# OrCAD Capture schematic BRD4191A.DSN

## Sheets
1 06: Antenna Array: size A3; title: BG22 Dual Polarized Antenna Array Radio Board; rev: A03; company: Silicon Labs; note: BRD4191A; note: TAB; note: JSH
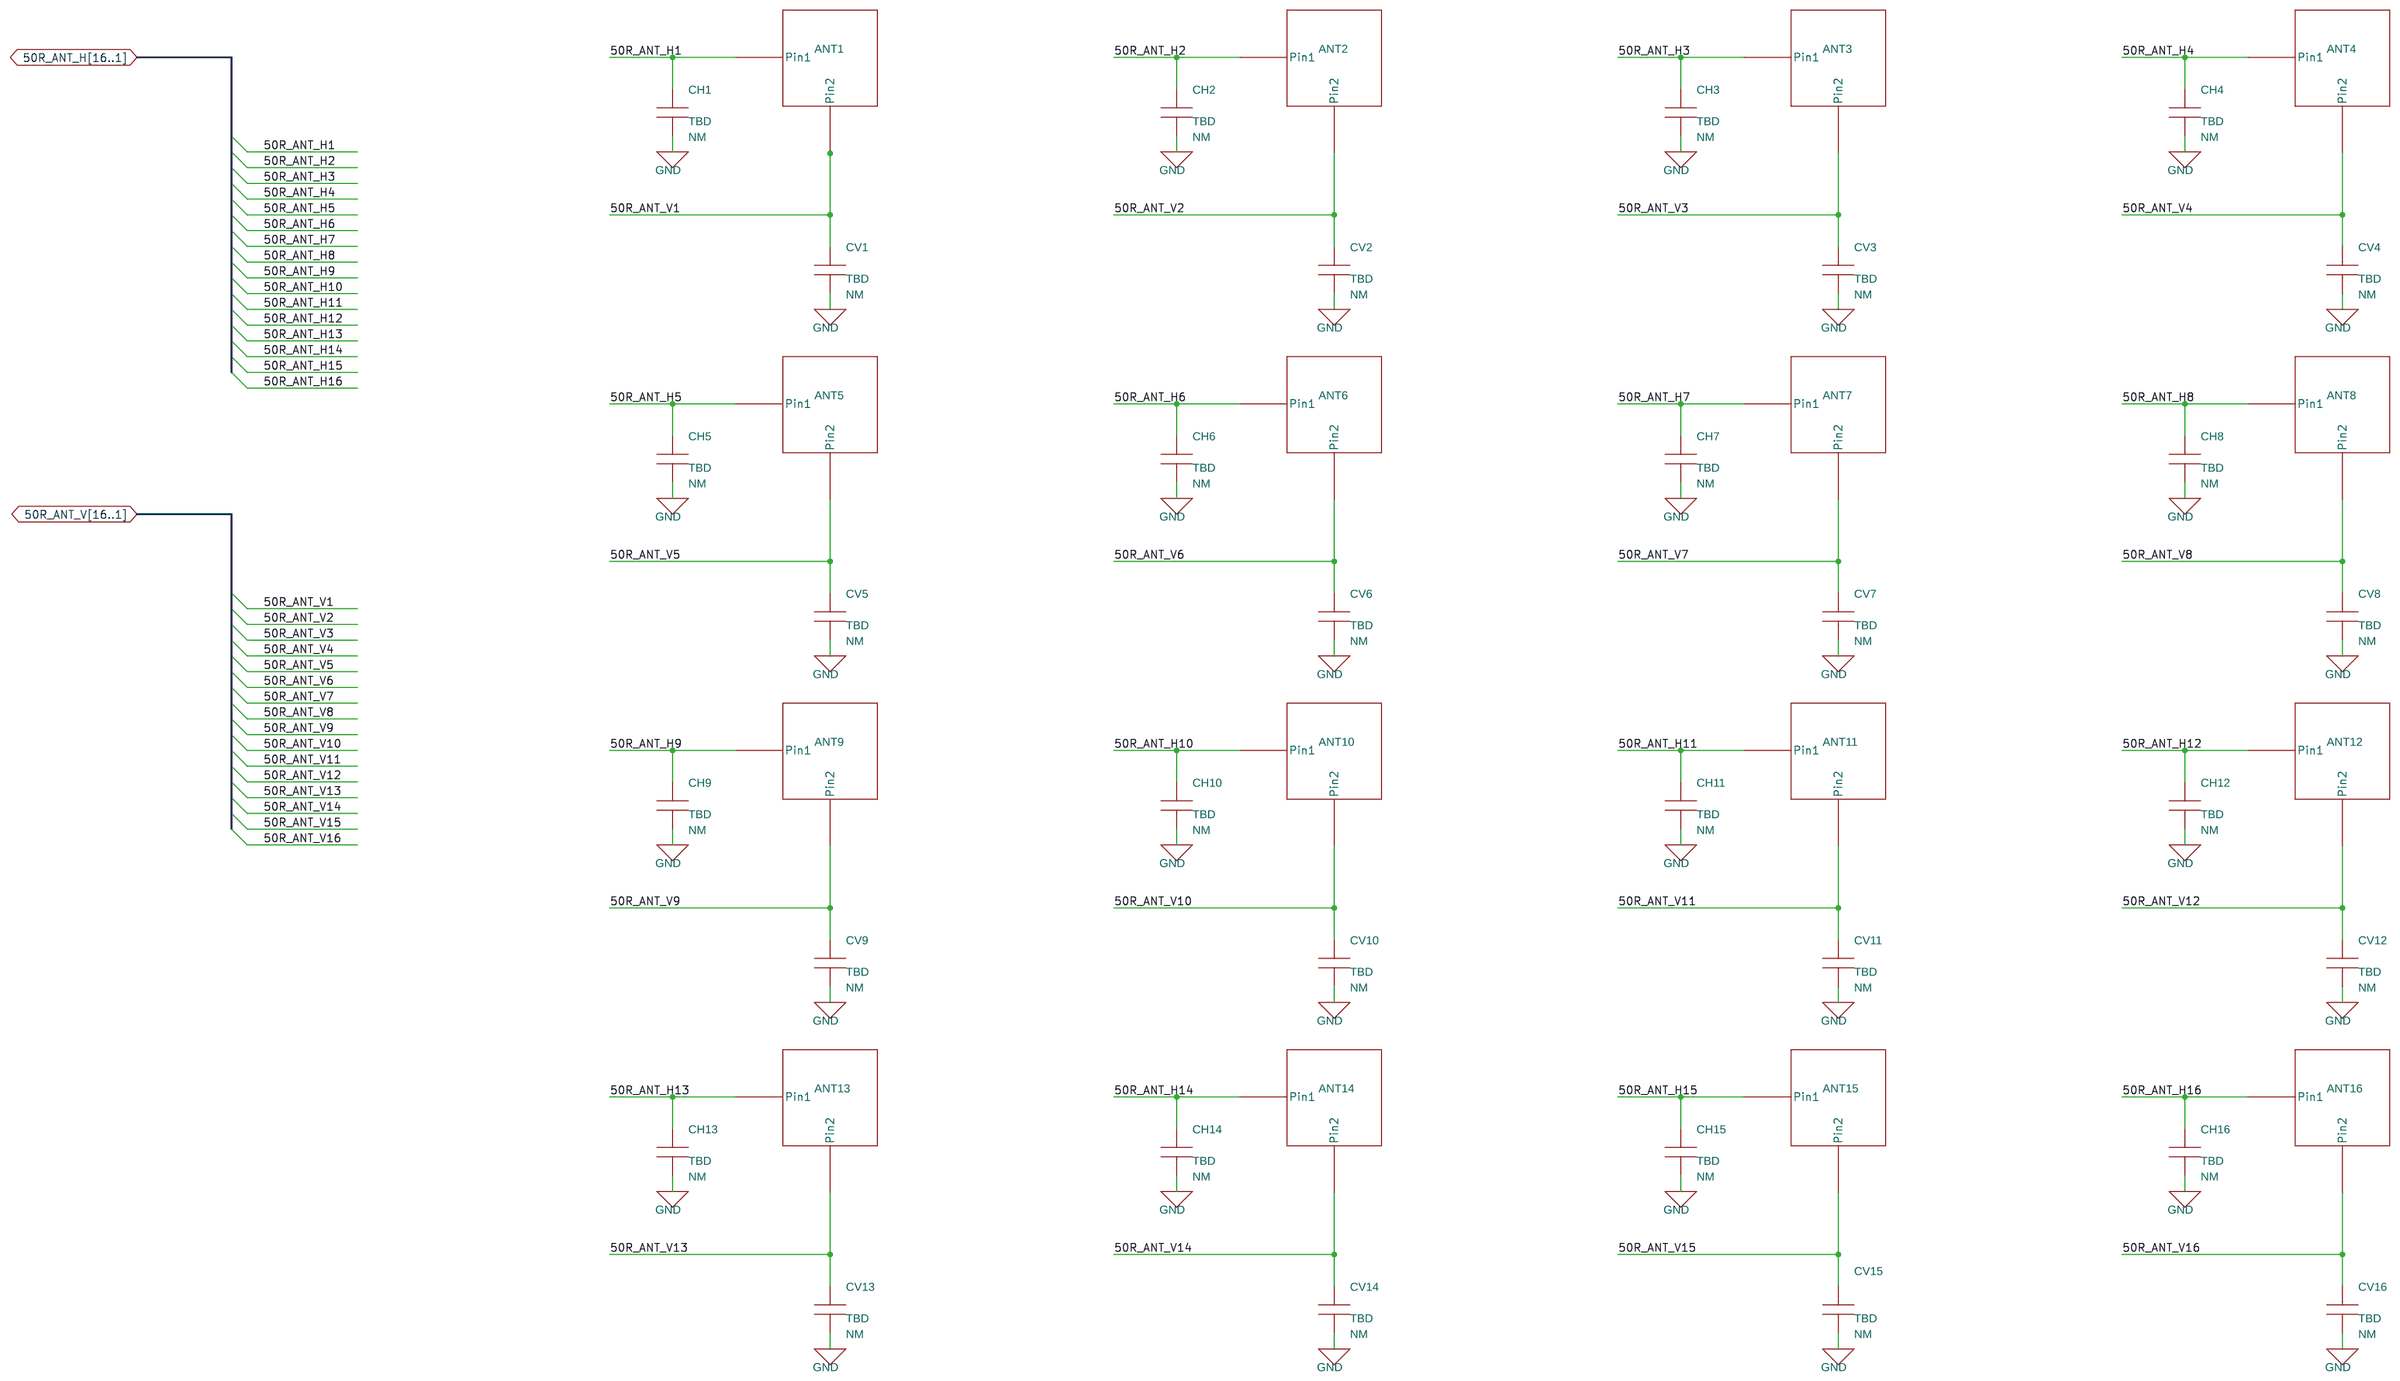
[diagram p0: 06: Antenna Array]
2 01: Title Page
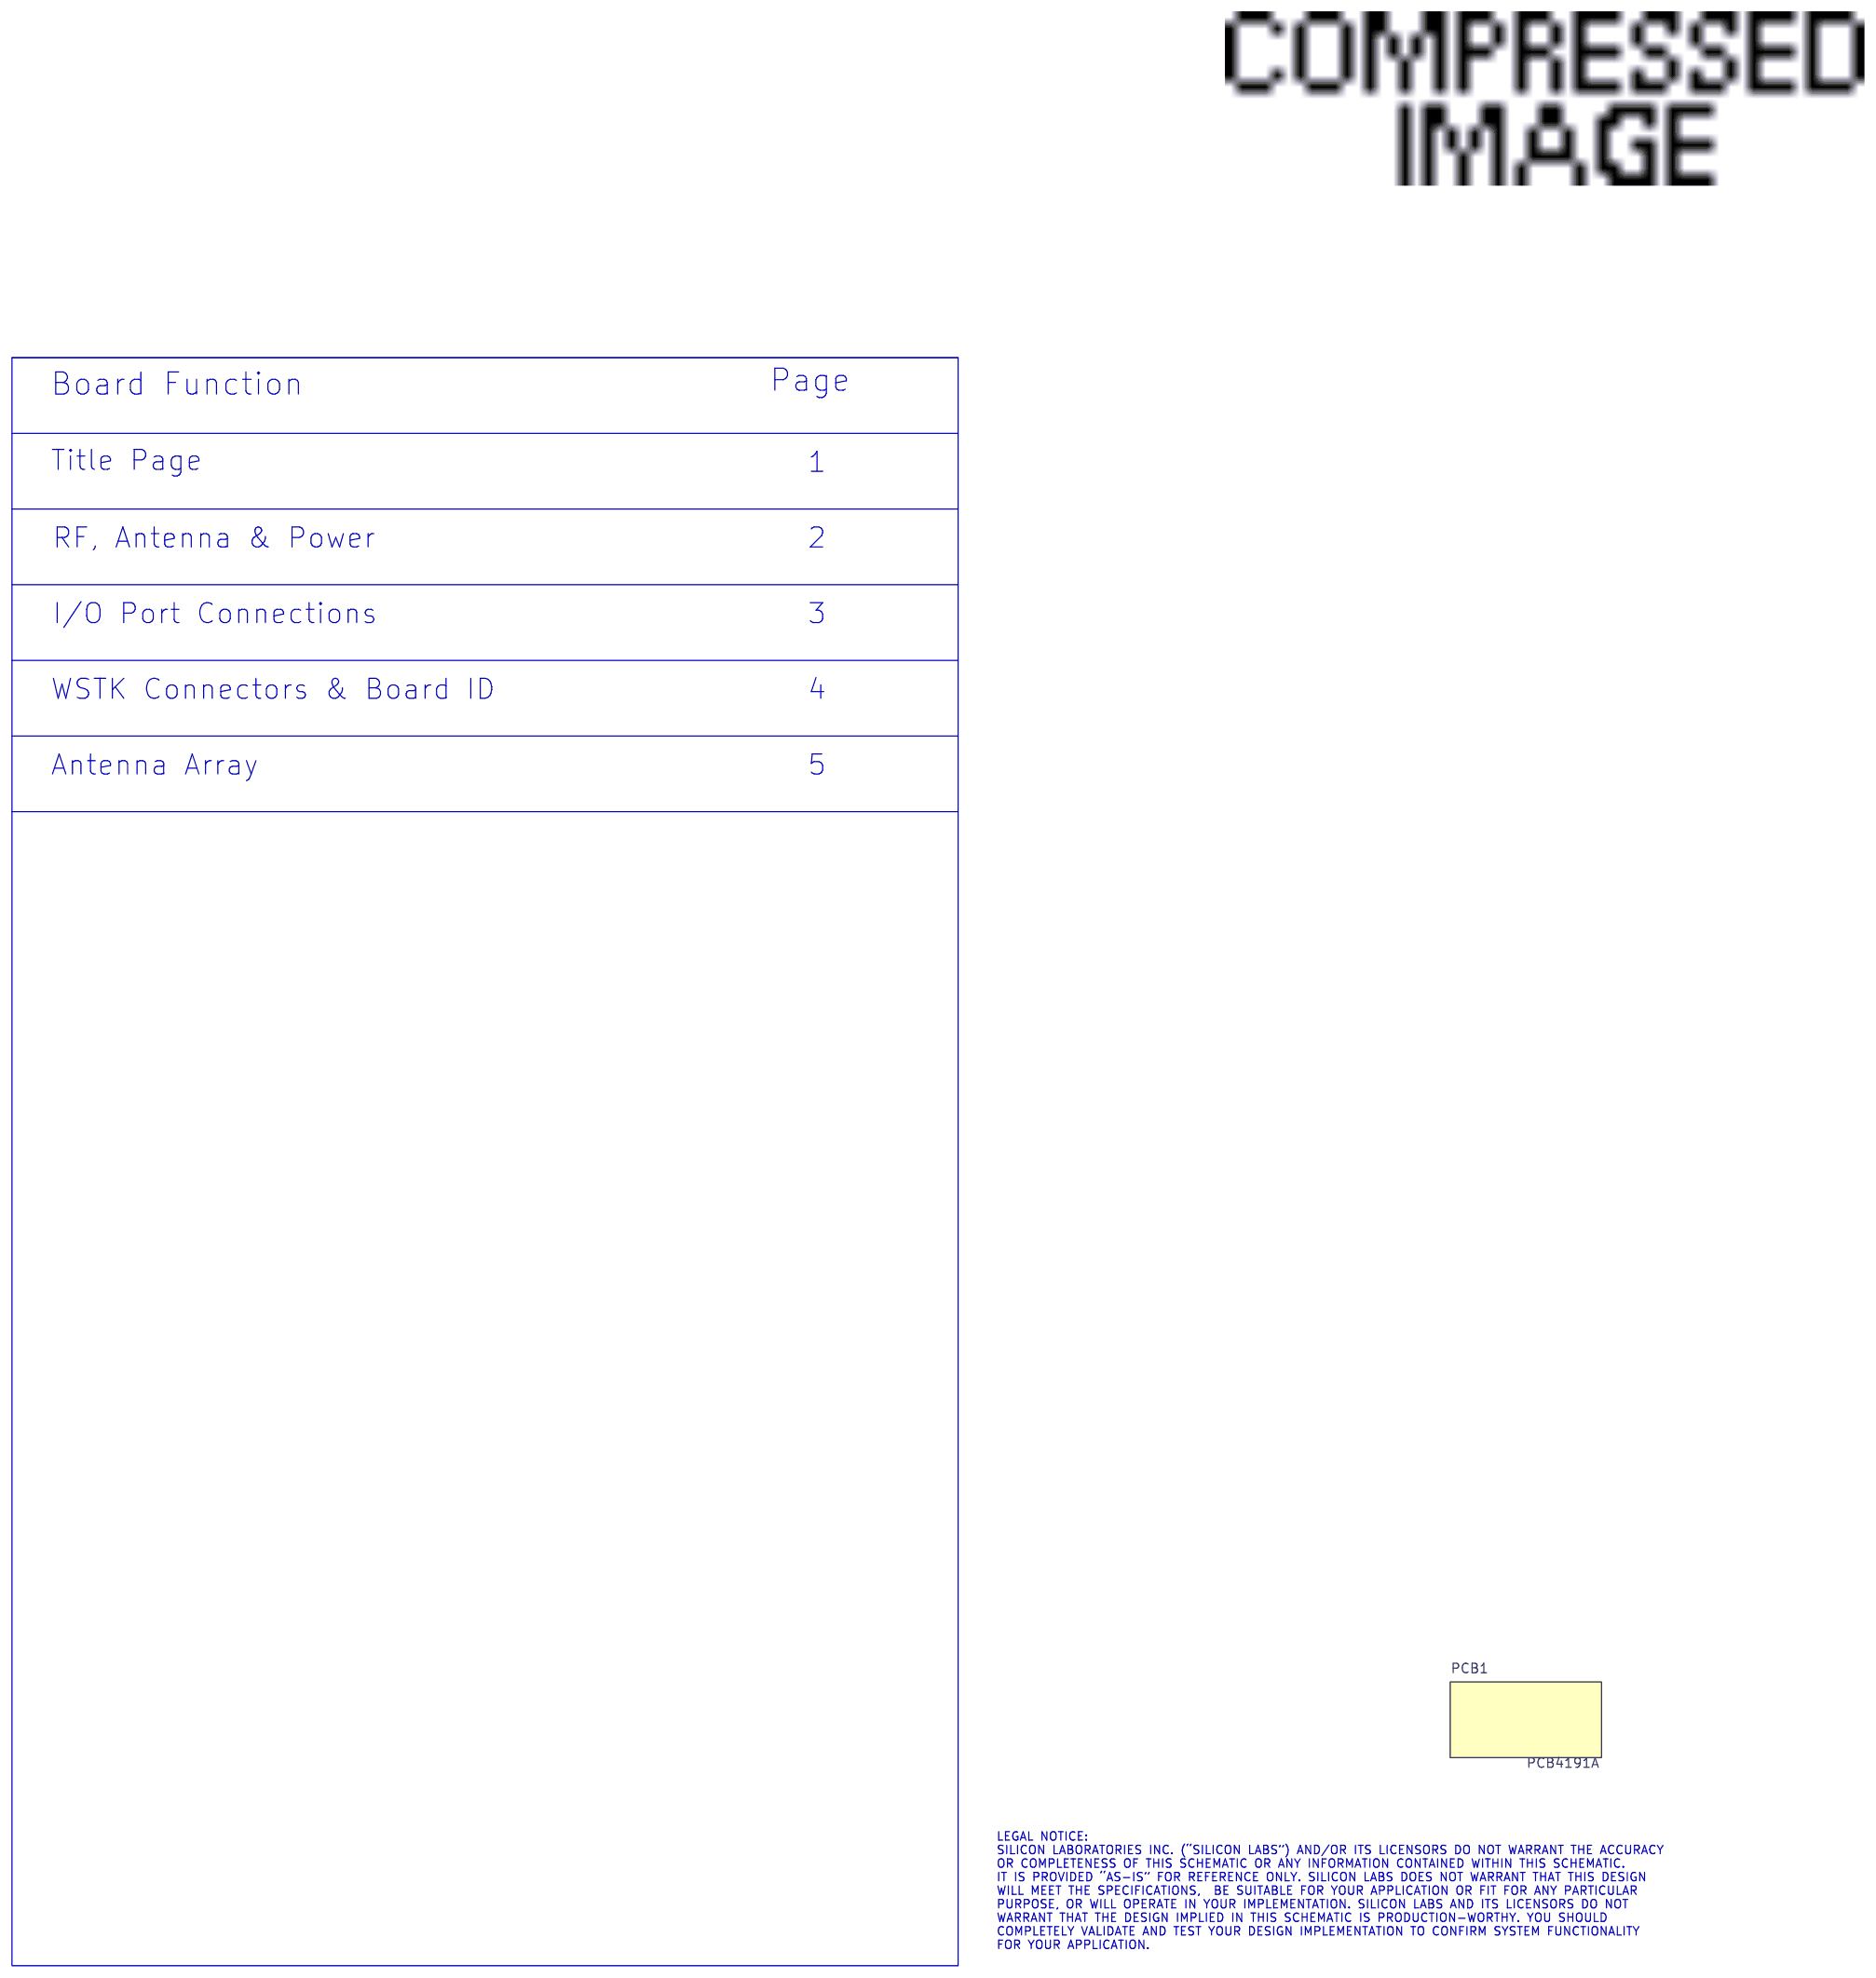
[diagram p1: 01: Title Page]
3 03: I/O Port Connections: size A3
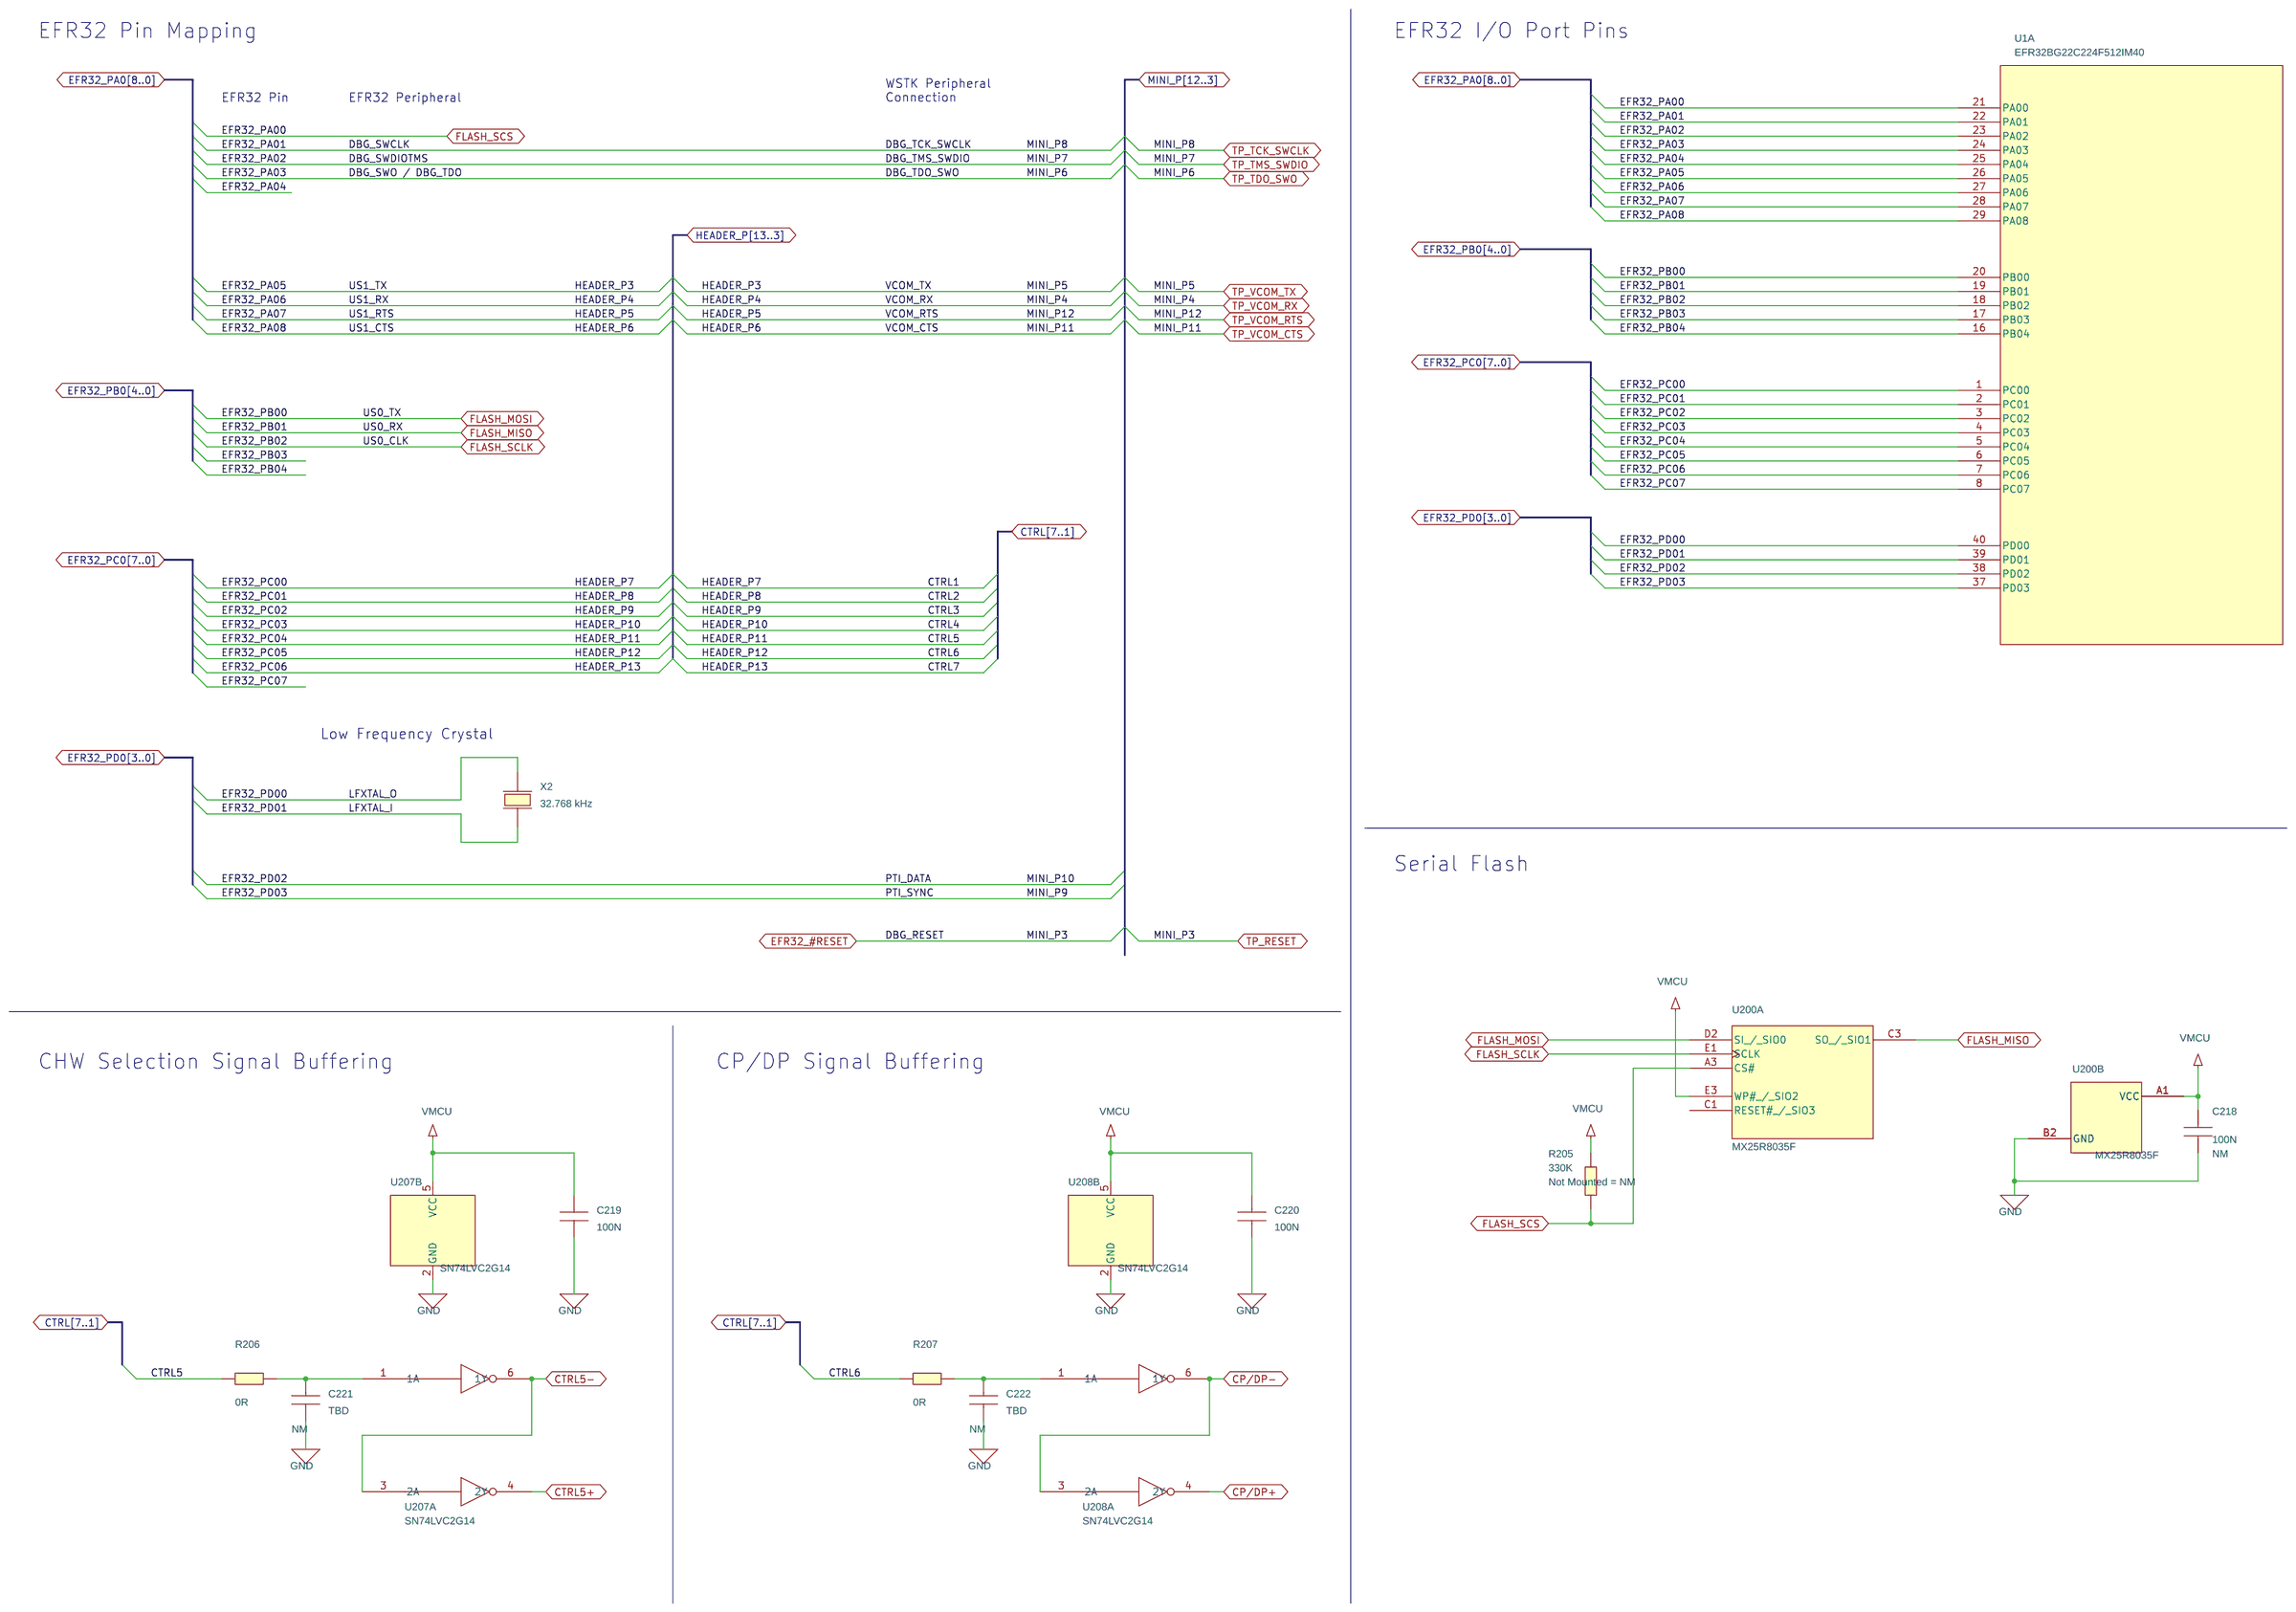
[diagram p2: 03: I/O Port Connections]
4 05: RF Feedline Network: size A3
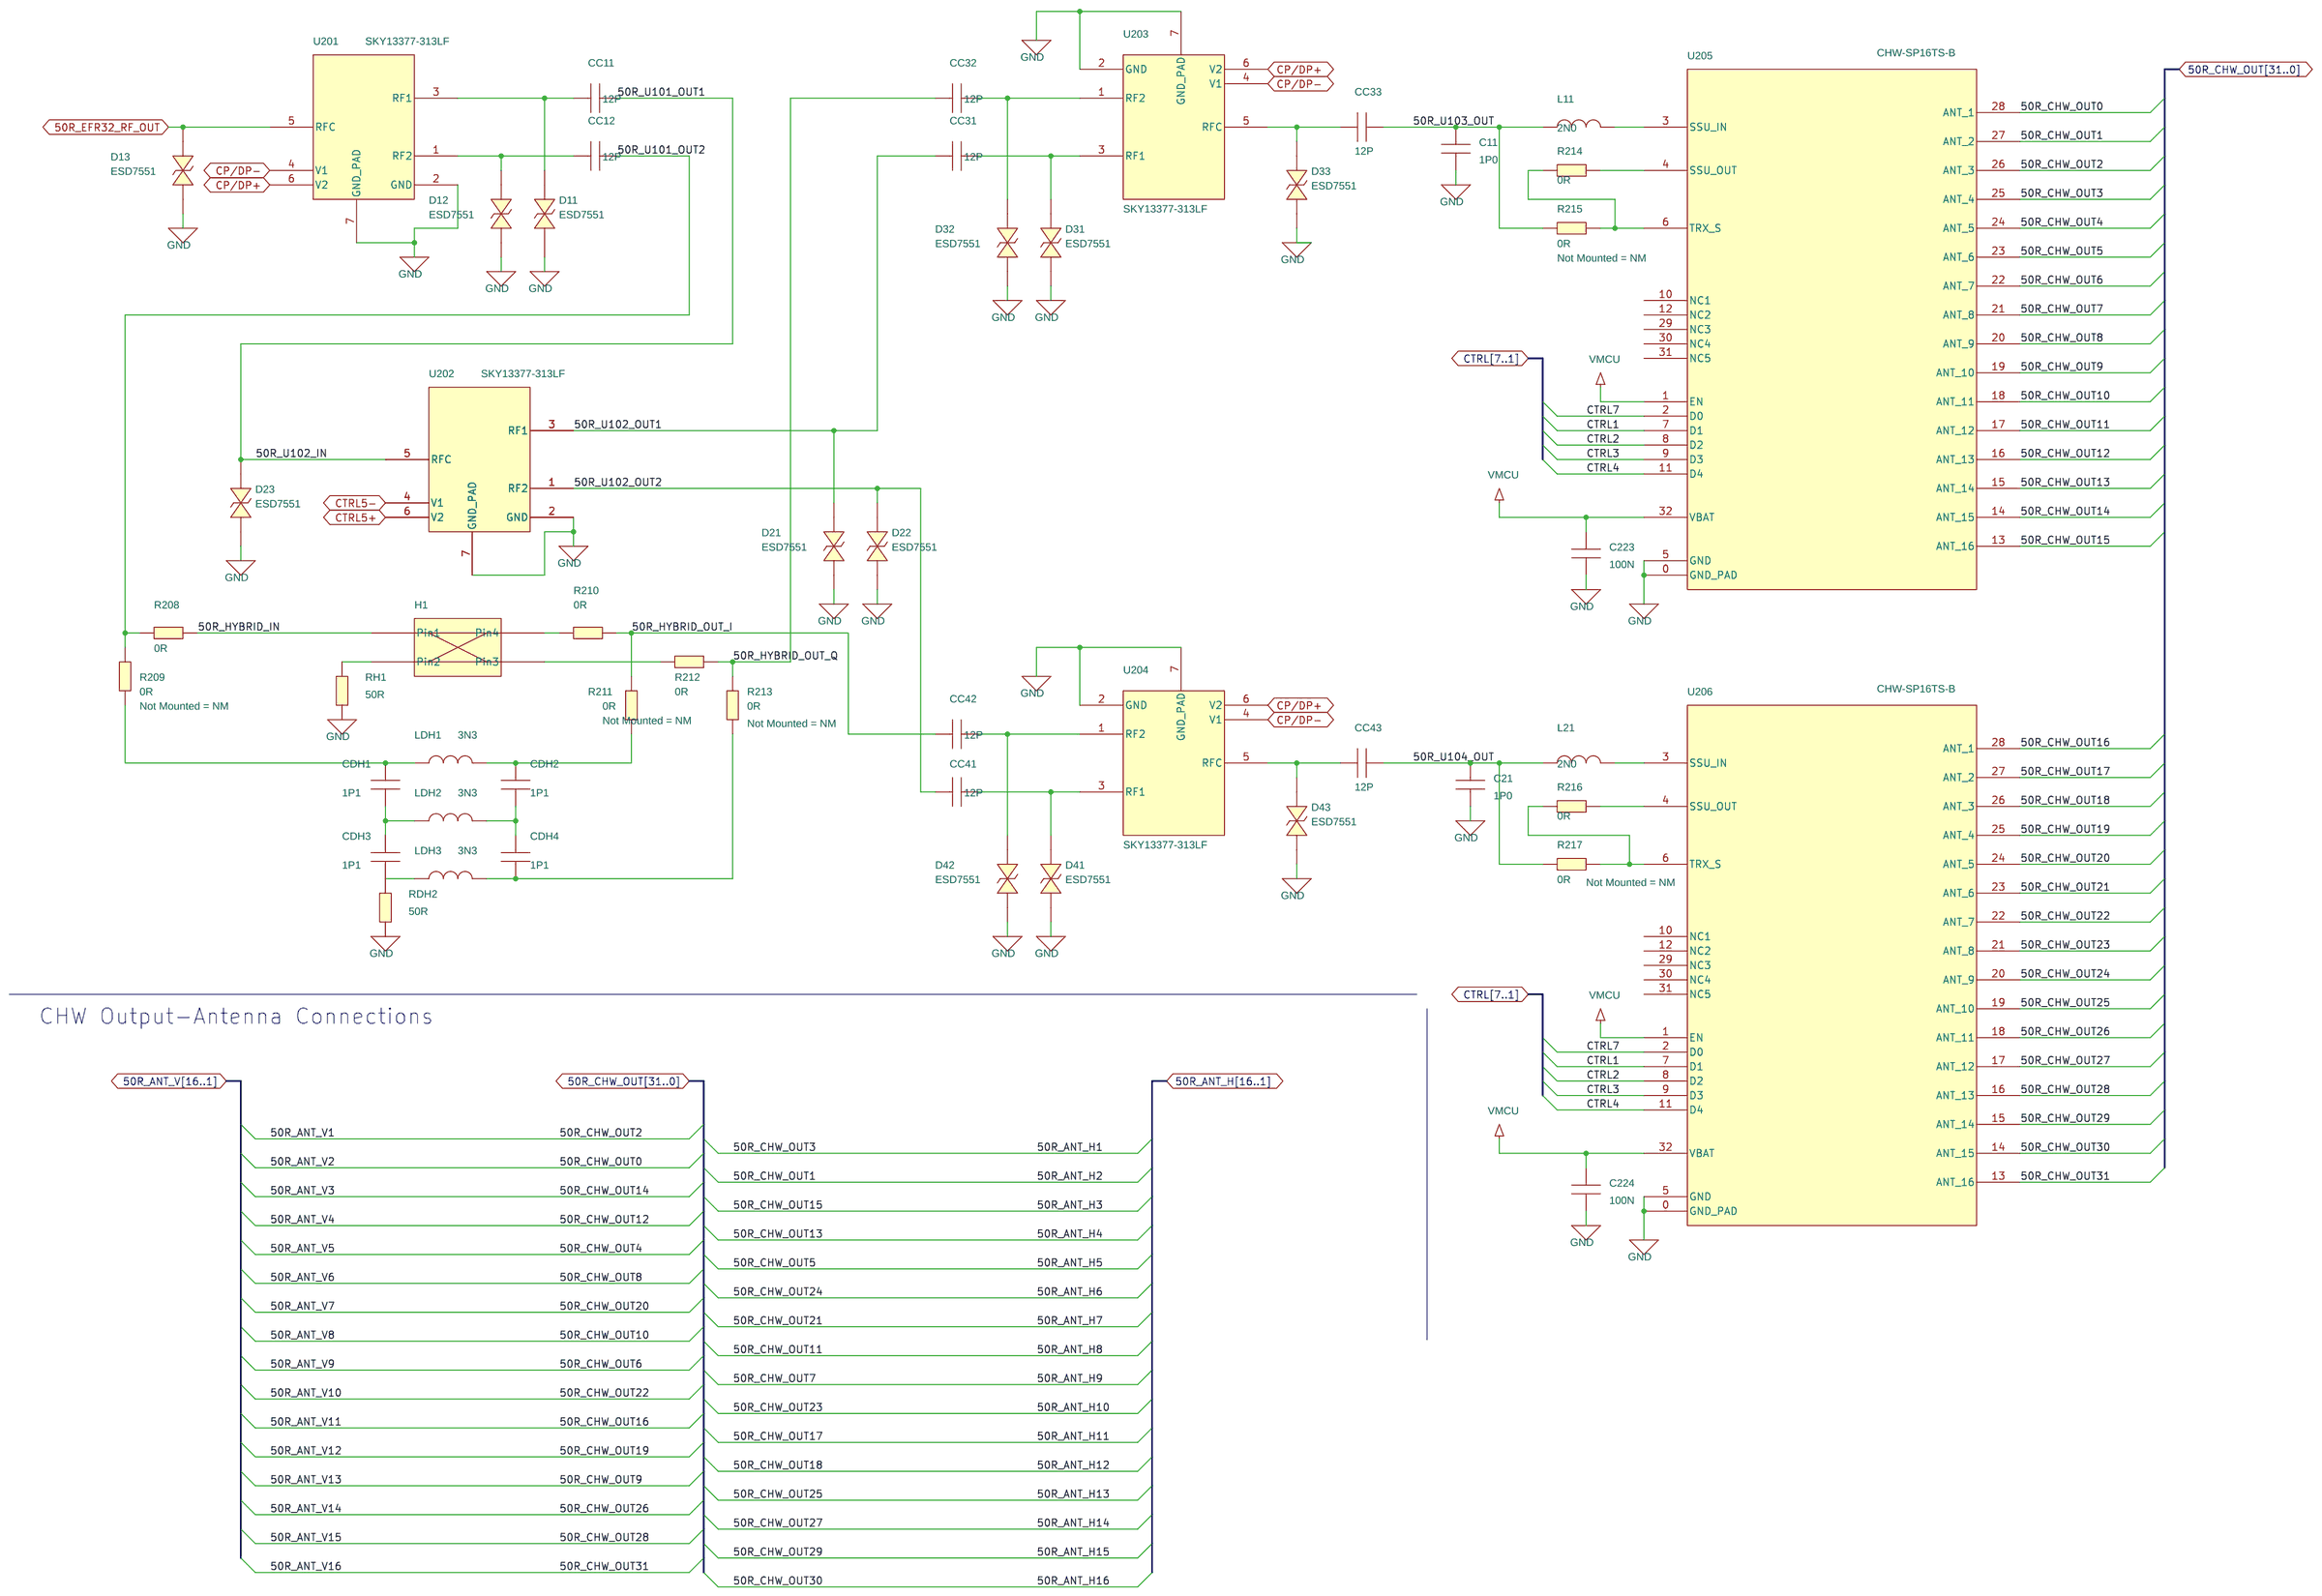
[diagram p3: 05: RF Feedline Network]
5 02: RF, Antenna and Power: size A3
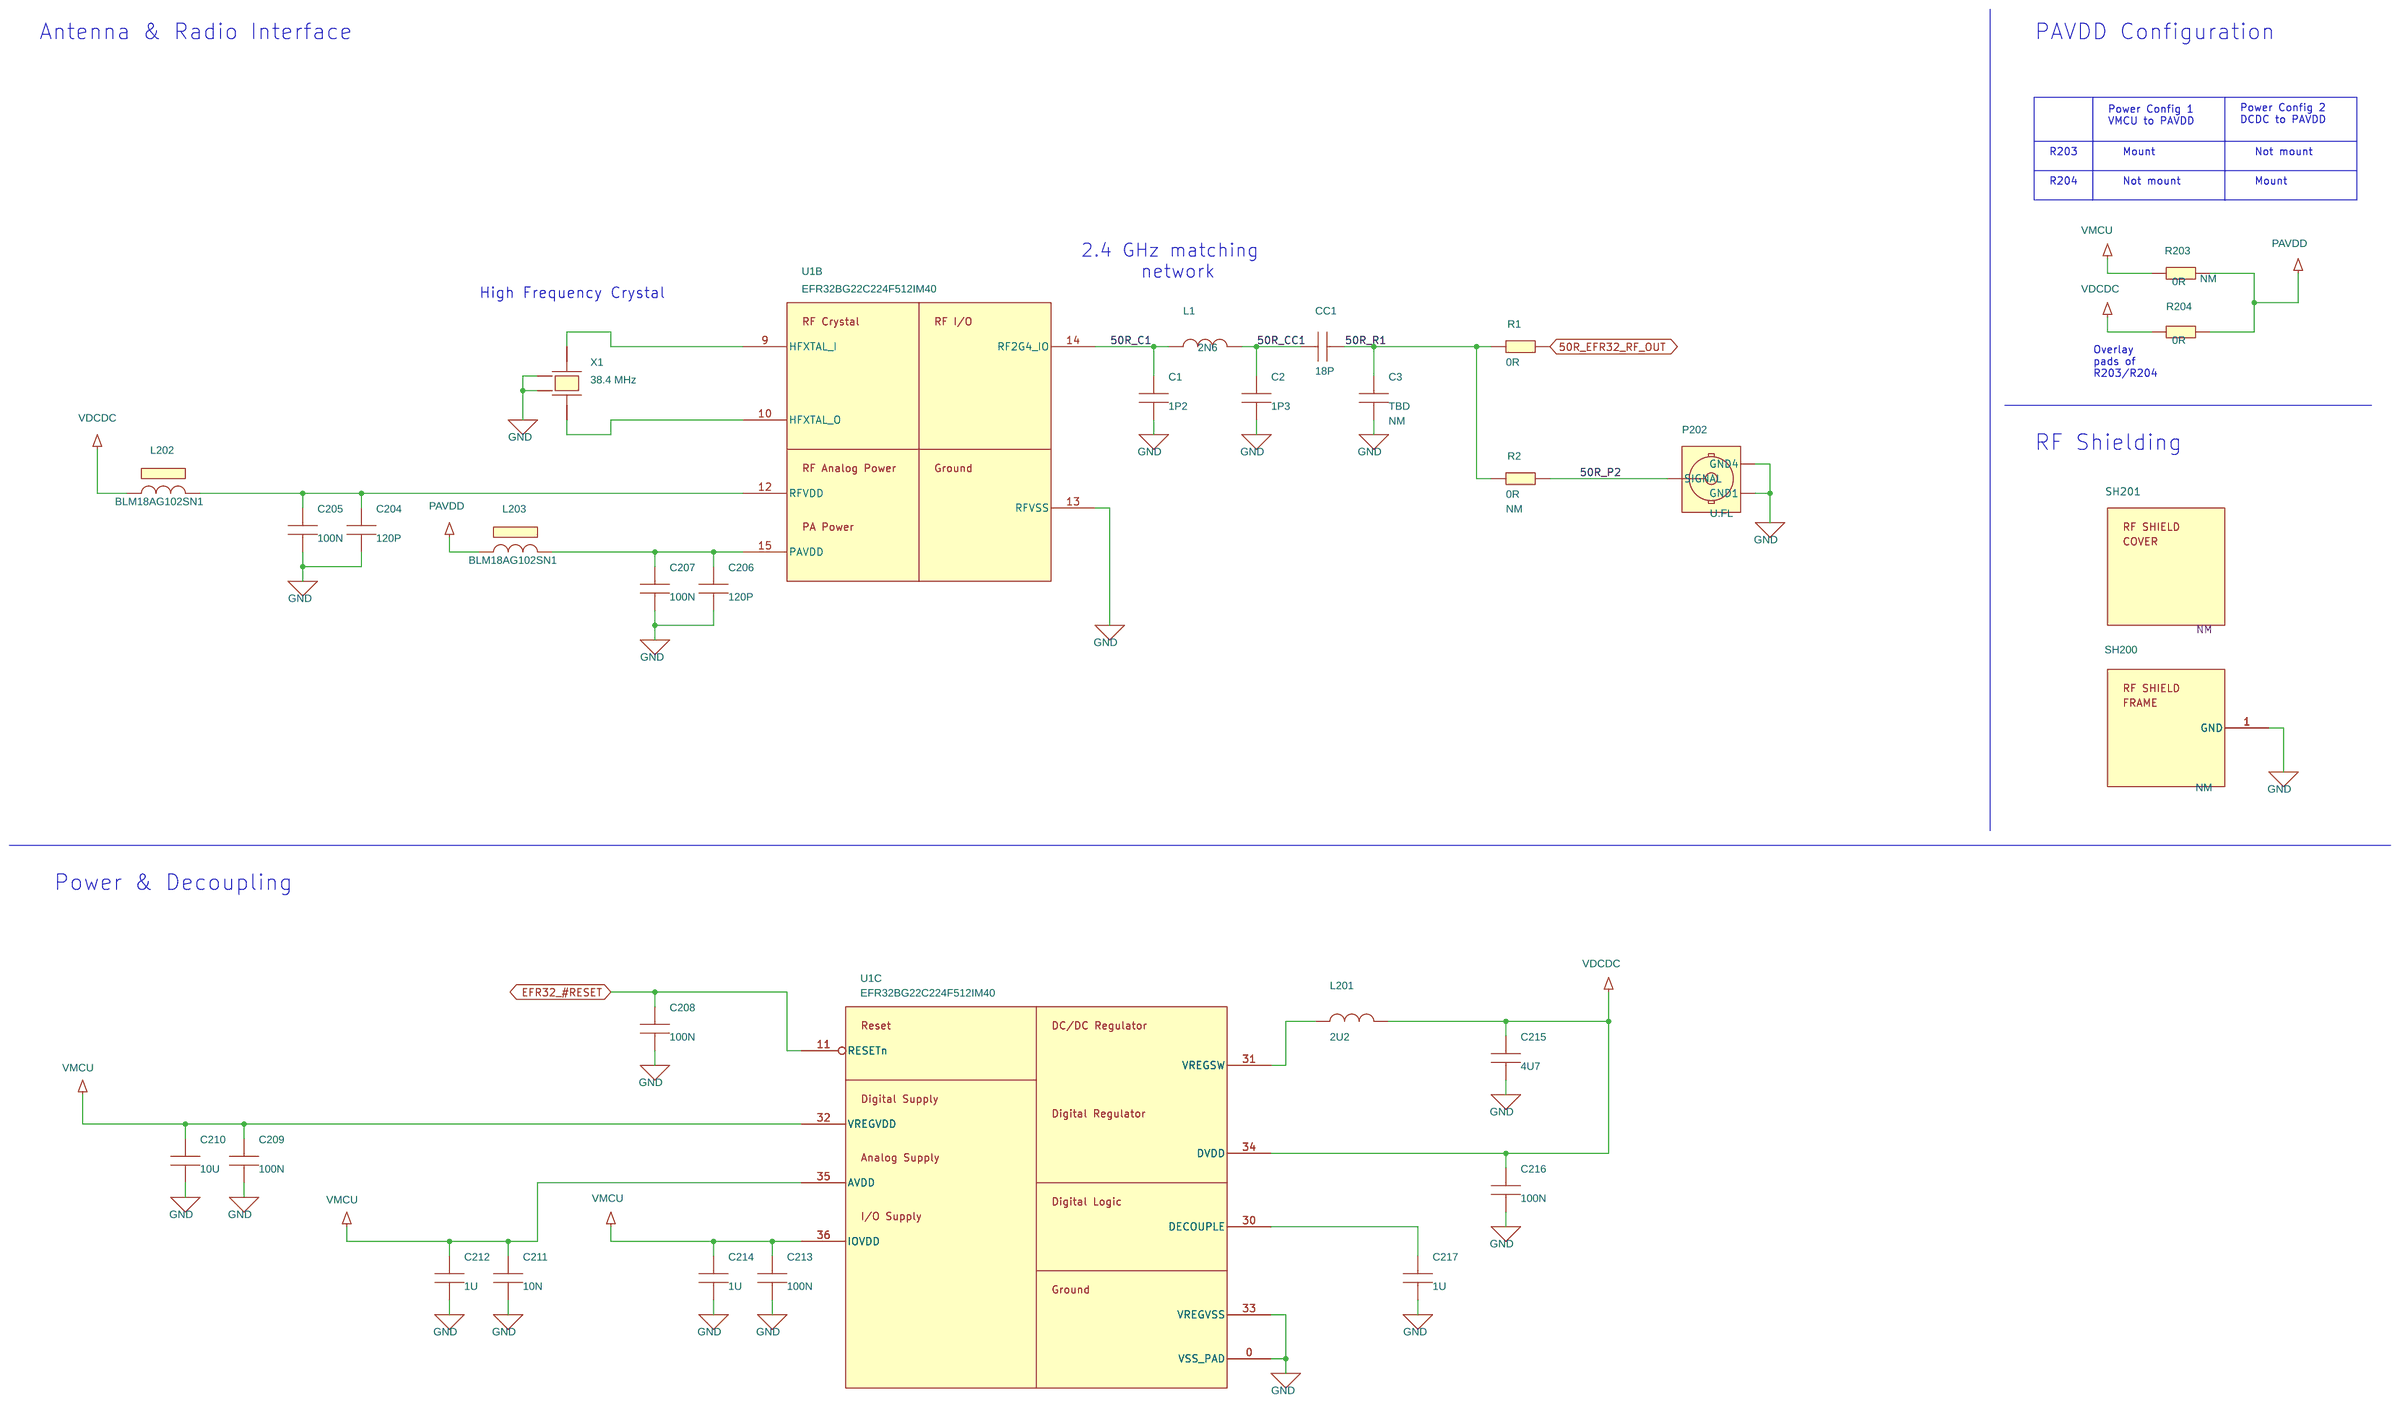
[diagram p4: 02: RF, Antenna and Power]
6 04: Board connection & TP: size A3
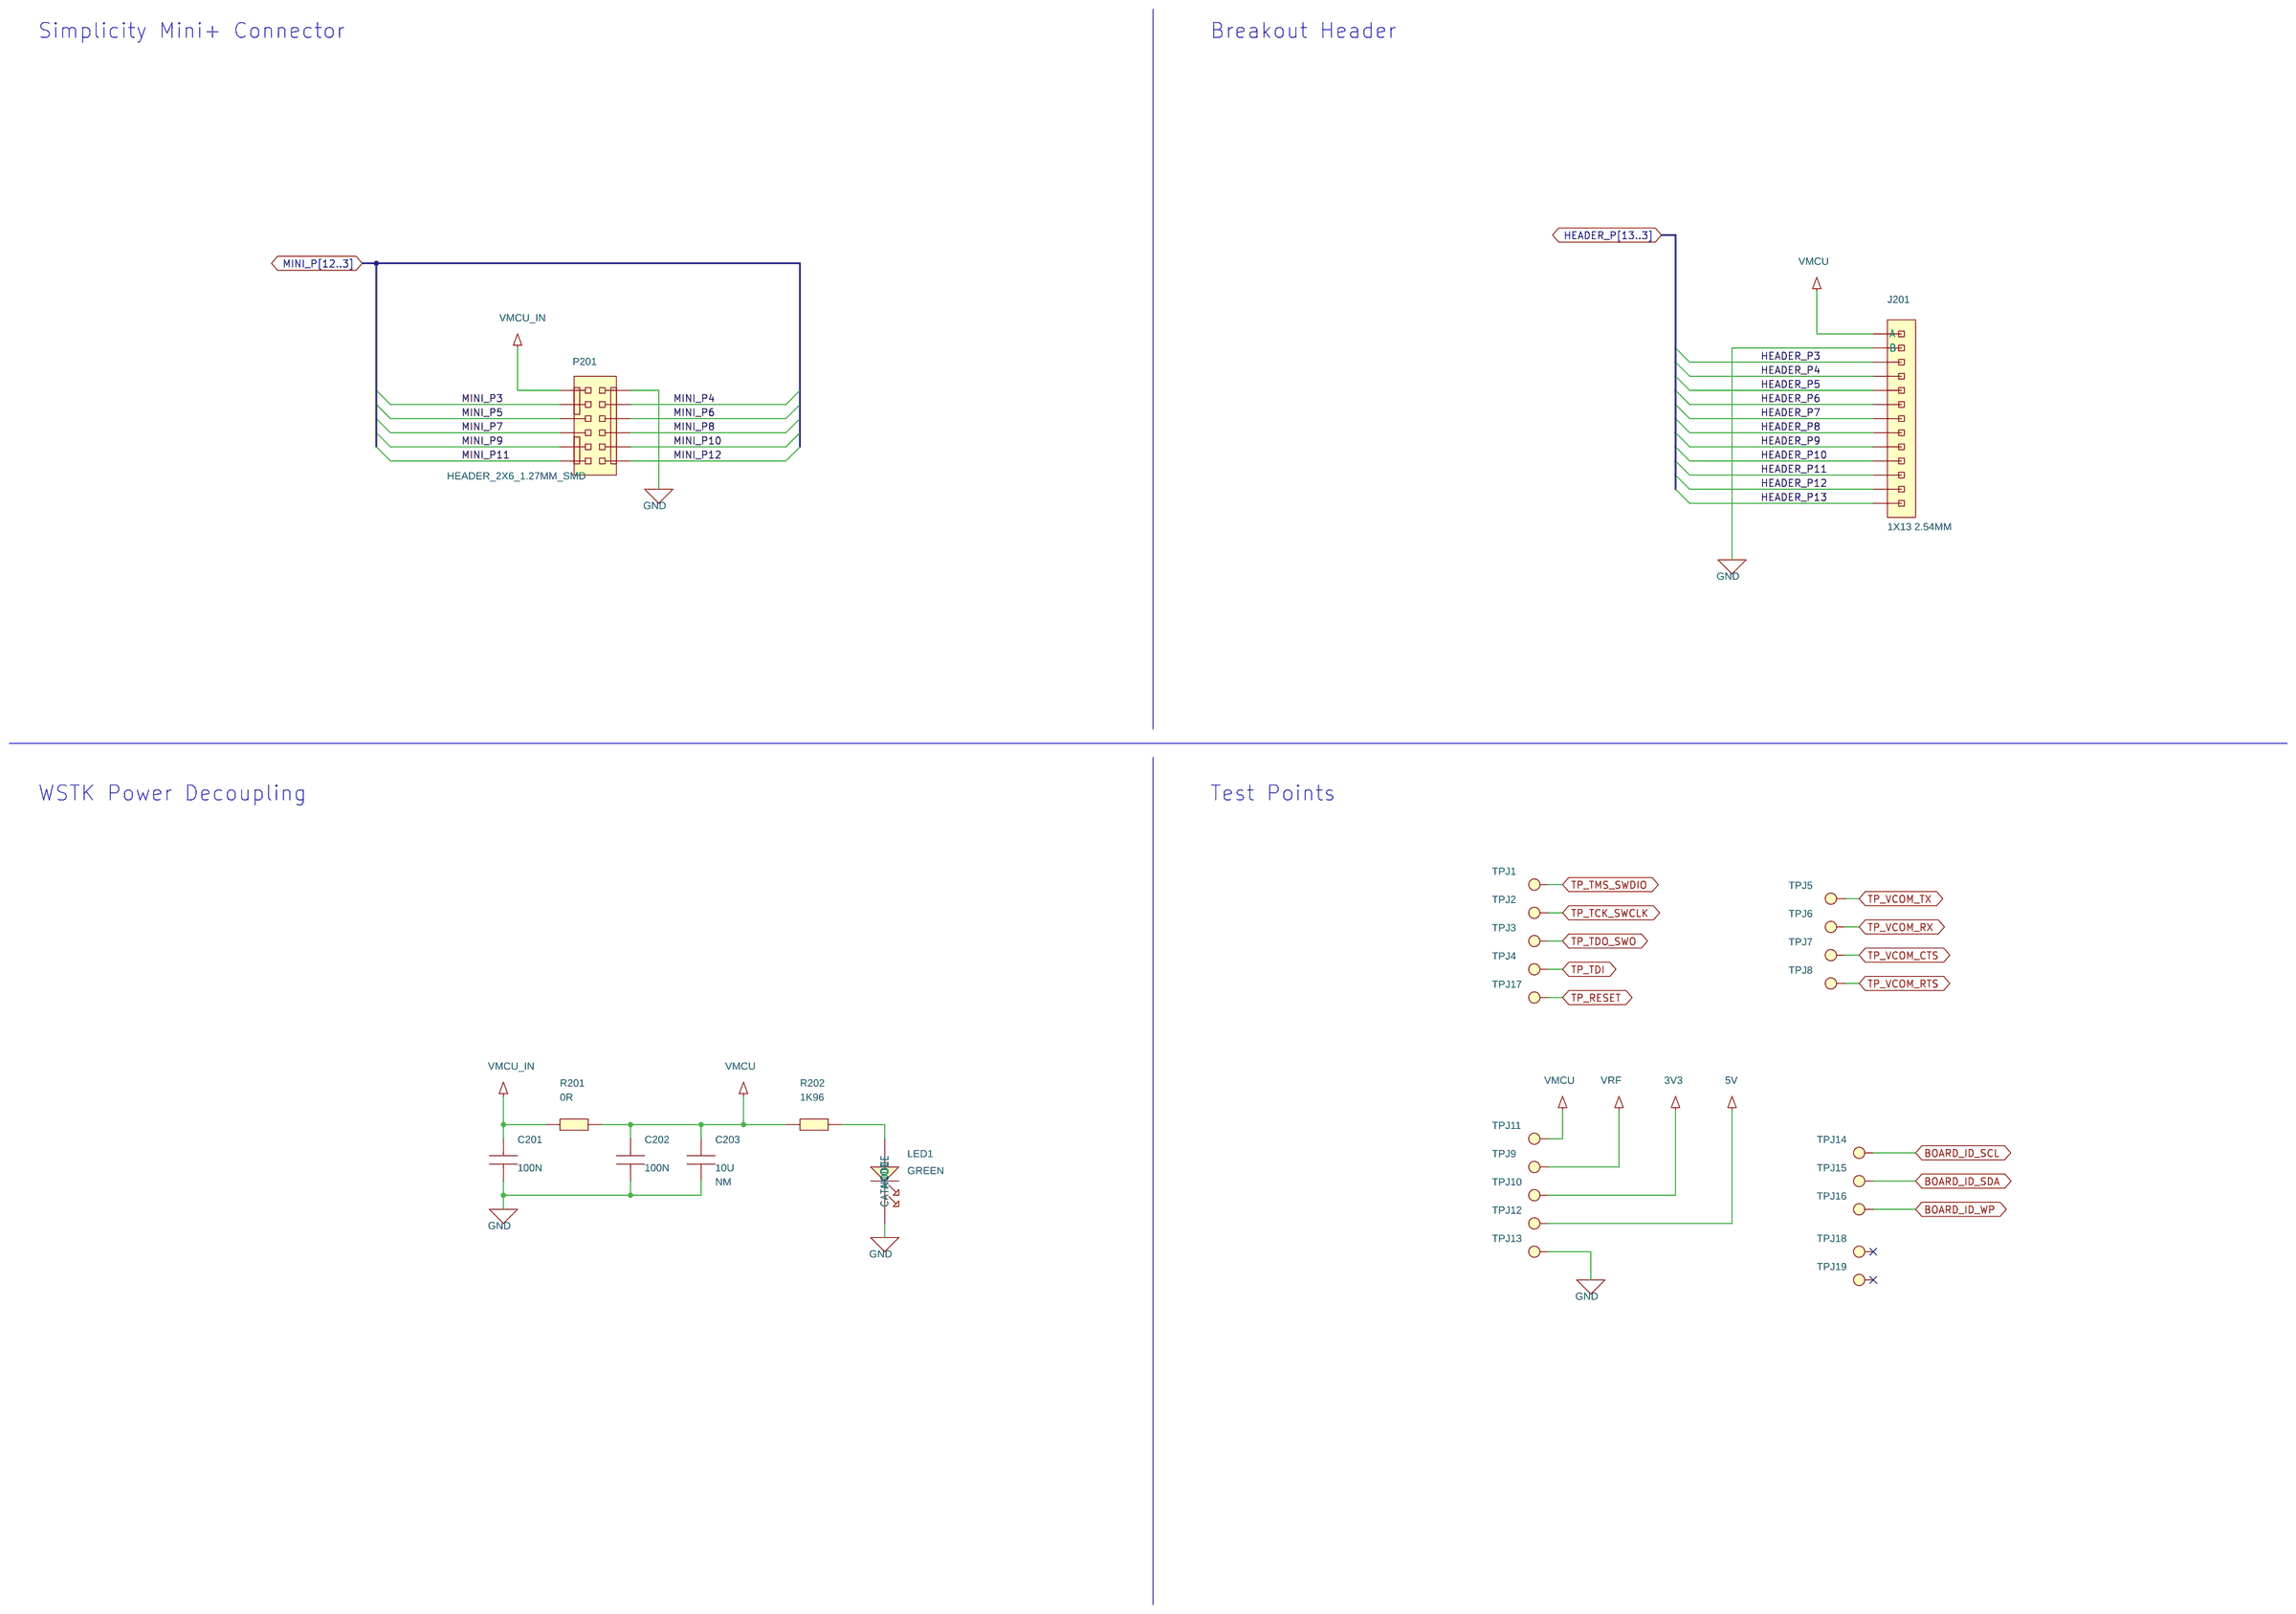
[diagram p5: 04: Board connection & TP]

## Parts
sheet 01: Title Page
PCB1  PCB4191A  [N/A]
sheet 02: RF, Antenna and Power
C1  1P2  [C0201_L]
C2  1P3  [C0201_L]
C3  TBD  [C0201_L]
C204  120P  [C0201_L]
C205  100N  [C0201_L]
C206  120P  [C0201_L]
C207  100N  [C0201_L]
C208  100N  [C0201_L]
C209  100N  [C0201_L]
C210  10U  [C0603_L]
C211  10N  [C0201_L]
C212  1U  [C0402_L]
C213  100N  [C0201_L]
C214  1U  [C0402_L]
C215  4U7  [C0603_L]
C216  100N  [C0201_L]
C217  1U  [C0201_L]
CC1  18P  [C0201_L]
L1  2N6  [COIL_0201_L]
L201  2U2  [COIL_1008_L]
L202  BLM18AG102SN1  [COIL_MUR_BLM18_0603]
L203  BLM18AG102SN1  [COIL_MUR_BLM18_0603]
P202  U.FL  [COAX_HIROSE_U.FL_CL331-0471]
R1  0R  [R0402_L]
R2  0R  [R0402_L]
R203  0R  [R0402_L]
R204  0R  [R0402_L]
SH200  RF_SHIELD_FRAME_BMI-S-202-F  [Laird_BMI-S-202-F]
SH201  RF_SHIELD_COVER_BMI-S-202-C
U1  EFR32BG22C224F512IM40  [QFN40_M040_5.0X5.0_EP_SL]  (sections A,B,C)
X1  38.4 MHz  [KDS_DSX211SH_2016]
sheet 03: I/O Port Connections
C218  100N  [C0201_L]
C219  100N  [C0402_L]
C220  100N  [C0402_L]
C221  TBD  [C0201_L]
C222  TBD  [C0201_L]
R205  330K  [R0201_L]
R206  0R  [R0201_L]
R207  0R  [R0201_L]
U200  MX25R8035F  [BGA8_M040_1.24x1.75_WLCSP]  (sections A,B)
U207  SN74LVC2G14  [SOT-23-6_SN74LVC2G14]  (sections A,B)
U208  SN74LVC2G14  [SOT-23-6_SN74LVC2G14]  (sections A,B)
X2  32.768 kHz  [X_MCS_CM8V-T1A]
sheet 04: Board connection & TP
C201  100N  [C0201_L]
C202  100N  [C0201_L]
C203  10U  [C0805_L]
J201  1X13 2.54MM  [HEADER_1X13_2.54MM_TH]
LED1  GREEN  [LED0402_L]
P201  HEADER_2X6_1.27MM_SMD  [FTSH_106_01_L_DV_K]
R201  0R  [R0402_L]
R202  1K96  [R0402_L]
TPJ1  TPJ_SMD  [TP_1.0_SMD]
TPJ2  TPJ_SMD  [TP_1.0_SMD]
TPJ3  TPJ_SMD  [TP_1.0_SMD]
TPJ4  TPJ_SMD  [TP_1.0_SMD]
TPJ5  TPJ_SMD  [TP_1.0_SMD]
TPJ6  TPJ_SMD  [TP_1.0_SMD]
TPJ7  TPJ_SMD  [TP_1.0_SMD]
TPJ8  TPJ_SMD  [TP_1.0_SMD]
TPJ9  TPJ_SMD  [TP_1.0_SMD]
TPJ10  TPJ_SMD  [TP_1.0_SMD]
TPJ11  TPJ_SMD  [TP_1.0_SMD]
TPJ12  TPJ_SMD  [TP_1.0_SMD]
TPJ13  TPJ_SMD  [TP_1.0_SMD]
TPJ14  TPJ_SMD  [TP_1.0_SMD]
TPJ15  TPJ_SMD  [TP_1.0_SMD]
TPJ16  TPJ_SMD  [TP_1.0_SMD]
TPJ17  TPJ_SMD  [TP_1.0_SMD]
TPJ18  TPJ_SMD  [TP_1.0_SMD]
TPJ19  TPJ_SMD  [TP_1.0_SMD]
sheet 05: RF Feedline Network
C11  1P0  [C0201_L]
C21  1P0  [C0201_L]
C223  100N  [C0402_L]
C224  100N  [C0402_L]
CC11  12P  [C0402_L]
CC12  12P  [C0402_L]
CC31  12P  [C0402_L]
CC32  12P  [C0402_L]
CC33  12P  [C0402_L]
CC41  12P  [C0402_L]
CC42  12P  [C0402_L]
CC43  12P  [C0402_L]
CDH1  1P1  [C0201_L]
CDH2  1P1  [C0201_L]
CDH3  1P1  [C0201_L]
CDH4  1P1  [C0201_L]
D11  ESD7551  [X2DFN2_1.0x0.6_0.65P]
D12  ESD7551  [X2DFN2_1.0x0.6_0.65P]
D13  ESD7551  [X2DFN2_1.0x0.6_0.65P]
D21  ESD7551  [X2DFN2_1.0x0.6_0.65P]
D22  ESD7551  [X2DFN2_1.0x0.6_0.65P]
D23  ESD7551  [X2DFN2_1.0x0.6_0.65P]
D31  ESD7551  [X2DFN2_1.0x0.6_0.65P]
D32  ESD7551  [X2DFN2_1.0x0.6_0.65P]
D33  ESD7551  [X2DFN2_1.0x0.6_0.65P]
D41  ESD7551  [X2DFN2_1.0x0.6_0.65P]
D42  ESD7551  [X2DFN2_1.0x0.6_0.65P]
D43  ESD7551  [X2DFN2_1.0x0.6_0.65P]
H1  90DEG_HYBRID_6LAYER  [90DEG_HYBRID_EUROCIRCUITS_6LAYER_0mm2]
L11  2N0  [R0201_L]
L21  2N0  [R0201_L]
LDH1  3N3  [COIL_0201_L]
LDH2  3N3  [COIL_0201_L]
LDH3  3N3  [COIL_0201_L]
R208  0R  [R0402_L]
R209  0R  [R0402_L]
R210  0R  [R0402_L]
R211  0R  [R0402_L]
R212  0R  [R0402_L]
R213  0R  [R0402_L]
R214  0R  [R0201_L]
R215  0R  [R0201_L]
R216  0R  [R0201_L]
R217  0R  [R0201_L]
RDH2  50R  [R0201_L]
RH1  50R  [R0402_L]
U201  SKY13377-313LF  [SKY13377-313LF]
U202  SKY13377-313LF  [SKY13377-313LF]
U203  SKY13377-313LF  [SKY13377-313LF]
U204  SKY13377-313LF  [SKY13377-313LF]
U205  CHW-SP16TS-B  [QFN32_4X4MM_CHW-SP16TS-B]
U206  CHW-SP16TS-B  [QFN32_4X4MM_CHW-SP16TS-B]
sheet 06: Antenna Array
ANT1  RECT_DP_PATCH_6LAYER_4x4_RIS  [6LAYER_RECT_DP_PATCH_24mm2_14mmRIS_31mm6CELL_6mm1FP]
ANT2  RECT_DP_PATCH_6LAYER_4x4_RIS  [6LAYER_RECT_DP_PATCH_24mm2_14mmRIS_31mm6CELL_6mm1FP]
ANT3  RECT_DP_PATCH_6LAYER_4x4_RIS  [6LAYER_RECT_DP_PATCH_24mm2_14mmRIS_31mm6CELL_6mm1FP]
ANT4  RECT_DP_PATCH_6LAYER_4x4_RIS  [6LAYER_RECT_DP_PATCH_24mm2_14mmRIS_31mm6CELL_6mm1FP]
ANT5  RECT_DP_PATCH_6LAYER_4x4_RIS  [6LAYER_RECT_DP_PATCH_24mm2_14mmRIS_31mm6CELL_6mm1FP]
ANT6  RECT_DP_PATCH_6LAYER_4x4_RIS  [6LAYER_RECT_DP_PATCH_24mm2_14mmRIS_31mm6CELL_6mm1FP]
ANT7  RECT_DP_PATCH_6LAYER_4x4_RIS  [6LAYER_RECT_DP_PATCH_24mm2_14mmRIS_31mm6CELL_6mm1FP]
ANT8  RECT_DP_PATCH_6LAYER_4x4_RIS  [6LAYER_RECT_DP_PATCH_24mm2_14mmRIS_31mm6CELL_6mm1FP]
ANT9  RECT_DP_PATCH_6LAYER_4x4_RIS  [6LAYER_RECT_DP_PATCH_24mm2_14mmRIS_31mm6CELL_6mm1FP]
ANT10  RECT_DP_PATCH_6LAYER_4x4_RIS  [6LAYER_RECT_DP_PATCH_24mm2_14mmRIS_31mm6CELL_6mm1FP]
ANT11  RECT_DP_PATCH_6LAYER_4x4_RIS  [6LAYER_RECT_DP_PATCH_24mm2_14mmRIS_31mm6CELL_6mm1FP]
ANT12  RECT_DP_PATCH_6LAYER_4x4_RIS  [6LAYER_RECT_DP_PATCH_24mm2_14mmRIS_31mm6CELL_6mm1FP]
ANT13  RECT_DP_PATCH_6LAYER_4x4_RIS  [6LAYER_RECT_DP_PATCH_24mm2_14mmRIS_31mm6CELL_6mm1FP]
ANT14  RECT_DP_PATCH_6LAYER_4x4_RIS  [6LAYER_RECT_DP_PATCH_24mm2_14mmRIS_31mm6CELL_6mm1FP]
ANT15  RECT_DP_PATCH_6LAYER_4x4_RIS  [6LAYER_RECT_DP_PATCH_24mm2_14mmRIS_31mm6CELL_6mm1FP]
ANT16  RECT_DP_PATCH_6LAYER_4x4_RIS  [6LAYER_RECT_DP_PATCH_24mm2_14mmRIS_31mm6CELL_6mm1FP]
CH1  TBD  [C0201_NOPASTE]
CH2  TBD  [C0201_NOPASTE]
CH3  TBD  [C0201_NOPASTE]
CH4  TBD  [C0201_NOPASTE]
CH5  TBD  [C0201_NOPASTE]
CH6  TBD  [C0201_NOPASTE]
CH7  TBD  [C0201_NOPASTE]
CH8  TBD  [C0201_NOPASTE]
CH9  TBD  [C0201_NOPASTE]
CH10  TBD  [C0201_NOPASTE]
CH11  TBD  [C0201_NOPASTE]
CH12  TBD  [C0201_NOPASTE]
CH13  TBD  [C0201_NOPASTE]
CH14  TBD  [C0201_NOPASTE]
CH15  TBD  [C0201_NOPASTE]
CH16  TBD  [C0201_NOPASTE]
CV1  TBD  [C0201_NOPASTE]
CV2  TBD  [C0201_NOPASTE]
CV3  TBD  [C0201_NOPASTE]
CV4  TBD  [C0201_NOPASTE]
CV5  TBD  [C0201_NOPASTE]
CV6  TBD  [C0201_NOPASTE]
CV7  TBD  [C0201_NOPASTE]
CV8  TBD  [C0201_NOPASTE]
CV9  TBD  [C0201_NOPASTE]
CV10  TBD  [C0201_NOPASTE]
CV11  TBD  [C0201_NOPASTE]
CV12  TBD  [C0201_NOPASTE]
CV13  TBD  [C0201_NOPASTE]
CV14  TBD  [C0201_NOPASTE]
CV15  TBD  [C0201_NOPASTE]
CV16  TBD  [C0201_NOPASTE]

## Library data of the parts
PCB1 = PCB: Mfg #: PCB4191A Rev. A01; Price_1K: 1.25
C1 = C0201_0: Mfg: Murata; Mfg #: GRM0335C1H1R2BA01D; Technology: C0G; Tolerance: ±0.1P
C2 = C0201_0: Mfg: Murata; Mfg #: GRM0335C1H1R3BA01D; Technology: C0G; Tolerance: ±0.1P
C3 C221 C222 CH1-CH16 CV1-CV16 = C0201_0: Not Mounted: NM
C204 C206 = C0201_0: Rating: 50V; Technology: C0G; Tolerance: 5%
C201 C202 C205 C207-C209 C213 C216 C219 C220 C223 C224 = C0201_0: Rating: 25V; Technology: X5R; Tolerance: 10%
C210 = C0603: Rating: 25V; Technology: X5R; Tolerance: 20%
C211 = C0201_0: Rating: 10V; Technology: X5R; Tolerance: 10%
C212 C214 = C0402_0: Rating: 25V; Technology: X5R; Tolerance: 10%
C215 = C0603: Rating: 6.3V; Technology: X5R; Tolerance: 20%
C217 = C0201_0: Rating: 10V; Technology: X5R; Tolerance: 20%
CC1 = C0201_0: Mfg: Murata; Mfg #: GJM0335C1E180GB01D; Technology: C0G; Tolerance: ±2%
L1 = L0201_0: Mfg: Murata; Mfg #: LQP03HQ2N6B02D; Tolerance: ±0.1N
L201 = L1008: Mfg: Samsung; Mfg #: CIG22H2R2MNE; Tolerance: +/-20%
L202 L203 = BLM21B102S
P202 = HIROSE_U.FL: Mfg: KLS; Mfg #: L-KLS1-IPEX-20279-001E-01
R1 R201 R202 = RESISTOR
R2 = RESISTOR: Not Mounted: NM
R203 R209 R211 R213 = R0402_0: Not Mounted: NM
R204 R208 R210 R212 RH1 = R0402_0
SH200 = RF_SHIELD_FRAME_BMI-S-202-F: Not Mounted: NM
SH201 = RF_SHIELD_COVER_BMI-S-202-C: Not Mounted: NM
U1 = EFR32xG22_QFN40_2G4: Mfg #: EFR32BG22C224F512IM40-CR
X1 = DSX211SH: Mfg: Tai-Saw Technology; Mfg #: TZ3398B; Price_1K: 0.512
C218 = C0201_0: Not Mounted: NM; Rating: 25V; Technology: X5R; Tolerance: 10%
R205 R215 R217 = R0201_0: Not Mounted: NM
R206 R207 R214 R216 RDH2 = R0201_0
U200 = MX25R8035_0
U207 U208 = SN74LVC2G14_SOT23_6: Mfg: Texas Instruments
X2 = CM8V-T1A: Mfg: Micro Crystal AG; Mfg #: CM8V-T1A-32.768KHZ-7PF-20PPM-TA-QC; Not Mounted: NM
C203 = CAPACITOR: Not Mounted: NM; Technology: X5R
J201 = HEADER_1X13_1.54MM_TH
LED1 = LED_0402: Mfg: Vishay; Mfg #: VLMG1500-GS08; Price_1K: 0.1
P201 = HEADER_2X6_1.27MM_SMD: Mfg: WCON; Mfg #: 3132-12MS0BK00R1
TPJ1-TPJ19 = TPJ_SMD
C11 C21 = C0201_0: Mfg: Murata; Mfg #: GRM0335C1H1R0BA01D; Tolerance: ±0.1P
CC11 CC12 CC31 CC32 CC41-CC43 = C0402_0: Tolerance: ±5%
CC33 = C0402_0: Mfg: Murata; Mfg #: GRM1555C1H120JA01; Tolerance: ±5%
CDH1-CDH4 = C0201_0: Tolerance: ±0.1P
D11-D13 D21-D23 D31-D33 D41-D43 = ESD7551_1
H1 = 90DEG_HYBRID_0
L11 L21 = L0201_0: Mfg: Murata; Mfg #: LQP03TN2N0B02D; Tolerance: ±0.1N
LDH1-LDH3 = L0201_0: Mfg #: LQP03TN3N3B02D; Tolerance: ±0.1N
U201-U204 = SKY13377-313LF_0
U205 U206 = CHW-SP16TS-B: MFG: CoreHW
ANT1-ANT16 = RECT_DP_PATCH_6LAYER_4x4_RIS_0

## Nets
3V3: TPJ10.1(TP)
5V: TPJ12.1(TP)
GND: C1.2 C2.2 C3.2 C11.1 C21.1 C201.2 C202.2 C203.2 C204.2 C205.2 C206.2 C207.2 C208.2 C209.2 C210.2 C211.2 C212.2 C213.2 C214.2 C215.2 C216.2 C217.2 C218.2 C219.1 C220.1 C221.1 C222.1 C223.1 C224.1 CH1.2 CH2.2 CH3.2 CH4.2 CH5.2 CH6.2 CH7.2 CH8.2 CH9.2 CH10.2 CH11.2 CH12.2 CH13.2 CH14.2 CH15.2 CH16.2 CV1.2 CV2.2 CV3.2 CV4.2 CV5.2 CV6.2 CV7.2 CV8.2 CV9.2 CV10.2 CV11.2 CV12.2 CV13.2 CV14.2 CV15.2 CV16.2 D11.1 D12.1 D13.1 D21.1 D22.1 D23.1 D31.1 D32.1 D33.1 D41.1 D42.1 D43.1 J201.2(B) LED1.1(CATHODE) P201.2 P202.2(GND1) P202.3(GND4) RDH2.2 RH1.2 SH200.1(GND) TPJ13.1(TP) U1.0(VSS_PAD) U1.13(RFVSS) U1.33(VREGVSS) U200.B2(GND) U201.2(GND) U201.7(GND_PAD) U202.2(GND) U202.7(GND_PAD) U203.2(GND) U203.7(GND_PAD) U204.2(GND) U204.7(GND_PAD) U205.0(GND_PAD) U205.5(GND) U206.0(GND_PAD) U206.5(GND) U207.2(GND) U208.2(GND) X1.2 X1.4
50R_ANT_H1: ANT1.1(Pin1) CH1.1 U205.25(ANT_4)
50R_ANT_H2: ANT2.1(Pin1) CH2.1 U205.27(ANT_2)
50R_ANT_H3: ANT3.1(Pin1) CH3.1 U205.13(ANT_16)
50R_ANT_H4: ANT4.1(Pin1) CH4.1 U205.15(ANT_14)
50R_ANT_H5: ANT5.1(Pin1) CH5.1 U205.23(ANT_6)
50R_ANT_H6: ANT6.1(Pin1) CH6.1 U206.20(ANT_9)
50R_ANT_H7: ANT7.1(Pin1) CH7.1 U206.23(ANT_6)
50R_ANT_H8: ANT8.1(Pin1) CH8.1 U205.17(ANT_12)
50R_ANT_H9: ANT9.1(Pin1) CH9.1 U205.21(ANT_8)
50R_ANT_H10: ANT10.1(Pin1) CH10.1 U206.21(ANT_8)
50R_ANT_H11: ANT11.1(Pin1) CH11.1 U206.27(ANT_2)
50R_ANT_H12: ANT12.1(Pin1) CH12.1 U206.26(ANT_3)
50R_ANT_H13: ANT13.1(Pin1) CH13.1 U206.19(ANT_10)
50R_ANT_H14: ANT14.1(Pin1) CH14.1 U206.17(ANT_12)
50R_ANT_H15: ANT15.1(Pin1) CH15.1 U206.15(ANT_14)
50R_ANT_H16: ANT16.1(Pin1) CH16.1 U206.14(ANT_15)
50R_ANT_V1: ANT1.2(Pin2) CV1.1 U205.26(ANT_3)
50R_ANT_V2: ANT2.2(Pin2) CV2.1 U205.28(ANT_1)
50R_ANT_V3: ANT3.2(Pin2) CV3.1 U205.14(ANT_15)
50R_ANT_V4: ANT4.2(Pin2) CV4.1 U205.16(ANT_13)
50R_ANT_V5: ANT5.2(Pin2) CV5.1 U205.24(ANT_5)
50R_ANT_V6: ANT6.2(Pin2) CV6.1 U205.20(ANT_9)
50R_ANT_V7: ANT7.2(Pin2) CV7.1 U206.24(ANT_5)
50R_ANT_V8: ANT8.2(Pin2) CV8.1 U205.18(ANT_11)
50R_ANT_V9: ANT9.2(Pin2) CV9.1 U205.22(ANT_7)
50R_ANT_V10: ANT10.2(Pin2) CV10.1 U206.22(ANT_7)
50R_ANT_V11: ANT11.2(Pin2) CV11.1 U206.28(ANT_1)
50R_ANT_V12: ANT12.2(Pin2) CV12.1 U206.25(ANT_4)
50R_ANT_V13: ANT13.2(Pin2) CV13.1 U205.19(ANT_10)
50R_ANT_V14: ANT14.2(Pin2) CV14.1 U206.18(ANT_11)
50R_ANT_V15: ANT15.2(Pin2) CV15.1 U206.16(ANT_13)
50R_ANT_V16: ANT16.2(Pin2) CV16.1 U206.13(ANT_16)
50R_C1: C1.1 L1.1 U1.14(RF2G4_IO)
50R_CC1: C2.1 CC1.1 L1.2
50R_EFR32_RF_OUT: D13.2 R1.2 U201.5(RFC)
50R_HYBRID_IN: H1.1(Pin1) R208.2
50R_HYBRID_OUT_I: CC42.2 R210.2 R211.2
50R_HYBRID_OUT_Q: CC32.2 R212.2 R213.2
50R_P2: P202.1(SIGNAL) R2.2
50R_R1: C3.1 CC1.2 R1.1 R2.1
50R_U101_OUT1: CC11.1 D23.2 U202.5(RFC)
50R_U101_OUT2: CC12.1 R208.1 R209.2
50R_U102_OUT1: CC31.2 D21.2 U202.3(RF1)
50R_U102_OUT2: CC41.2 D22.2 U202.1(RF2)
50R_U103_OUT: C11.2 CC33.1 L11.1 R215.1
50R_U104_OUT: C21.2 CC43.1 L21.1 R217.1
BOARD_ID_SCL: TPJ14.1(TP)
BOARD_ID_SDA: TPJ15.1(TP)
BOARD_ID_WP: TPJ16.1(TP)
CP/DP+: U201.6(V2) U203.6(V2) U204.6(V2) U208.4(2Y)
CP/DP-: U201.4(V1) U203.4(V1) U204.4(V1) U208.3(2A) U208.6(1Y)
CTRL1: J201.7 U1.1(PC00) U205.7(D1) U206.7(D1)
CTRL2: J201.8 U1.2(PC01) U205.8(D2) U206.8(D2)
CTRL3: J201.9 U1.3(PC02) U205.9(D3) U206.9(D3)
CTRL4: J201.10 U1.4(PC03) U205.11(D4) U206.11(D4)
CTRL5: J201.11 R206.1 U1.5(PC04)
CTRL5+: U202.6(V2) U207.4(2Y)
CTRL5-: U202.4(V1) U207.3(2A) U207.6(1Y)
CTRL6: J201.12 R207.1 U1.6(PC05)
CTRL7: J201.13 U1.7(PC06) U205.2(D0) U206.2(D0)
EFR32_#RESET: C208.1 P201.3 TPJ17.1(TP) U1.11(RESETn)
EFR32_PA00: R205.1 U1.21(PA00) U200.A3(CS#)
EFR32_PA01: P201.8 TPJ2.1(TP) U1.22(PA01)
EFR32_PA02: P201.7 TPJ1.1(TP) U1.23(PA02)
EFR32_PA03: P201.6 TPJ3.1(TP) U1.24(PA03)
EFR32_PA04: U1.25(PA04)
EFR32_PA05: J201.3 P201.5 TPJ5.1(TP) U1.26(PA05)
EFR32_PA06: J201.4 P201.4 TPJ6.1(TP) U1.27(PA06)
EFR32_PA07: J201.5 P201.12 TPJ8.1(TP) U1.28(PA07)
EFR32_PA08: J201.6 P201.11 TPJ7.1(TP) U1.29(PA08)
EFR32_PB00: U1.20(PB00) U200.D2(SI_/_SIO0)
EFR32_PB01: U1.19(PB01) U200.C3(SO_/_SIO1)
EFR32_PB02: U1.18(PB02) U200.E1(SCLK)
EFR32_PB03: U1.17(PB03)
EFR32_PB04: U1.16(PB04)
EFR32_PC07: U1.8(PC07)
EFR32_PD00: U1.40(PD00) X2.1
EFR32_PD01: U1.39(PD01) X2.2
EFR32_PD02: P201.10 U1.38(PD02)
EFR32_PD03: P201.9 U1.37(PD03)
PAVDD: L203.1 R203.1 R204.2
TP_TDI: TPJ4.1(TP)
VDCDC: C215.1 C216.1 L201.2 L202.1 R204.1 U1.34(DVDD)
VMCU: C202.1 C203.1 C209.1 C210.1 C211.1 C212.1 C213.1 C214.1 C218.1 C219.2 C220.2 C223.2 C224.2 J201.1(A) R201.2 R202.1 R203.2 R205.2 TPJ11.1(TP) U1.32(VREGVDD) U1.35(AVDD) U1.36(IOVDD) U200.A1(VCC) U200.E3(WP#_/_SIO2) U205.1(EN) U205.32(VBAT) U206.1(EN) U206.32(VBAT) U207.5(VCC) U208.5(VCC)
VMCU_IN: C201.1 P201.1 R201.1
VRF: TPJ9.1(TP)
N16816371: L201.1 U1.31(VREGSW)
N16816400: C217.1 U1.30(DECOUPLE)
N16816410: U1.9(HFXTAL_I) X1.3
N16816441: U1.10(HFXTAL_O) X1.1
N16816744: C204.1 C205.1 L202.2 U1.12(RFVDD)
N16816775: C206.1 C207.1 L203.2 U1.15(PAVDD)
N16857153: CC11.2 D11.2 U201.3(RF1)
N16857156: CC12.2 D12.2 U201.1(RF2)
N16857328: H1.2(Pin2) RH1.1
N16857331: CDH1.1 LDH1.1 R209.1
N16857342: CDH2.1 LDH1.2 R211.1
N16857347: CDH2.2 CDH4.1 LDH2.2
N16857354: CDH1.2 CDH3.1 LDH2.1
N16857397: CDH4.2 LDH3.2 R213.1
N16857402: H1.4(Pin4) R210.1
N16857405: H1.3(Pin3) R212.1
N16857668: CC31.1 D31.2 U203.3(RF1)
N16857679: CC32.1 D32.2 U203.1(RF2)
N16857715: CC41.1 D41.2 U204.3(RF1)
N16857764: CC42.1 D42.2 U204.1(RF2)
N16857781: CC33.2 D33.2 U203.5(RFC)
N16857793: L11.2 U205.3(SSU_IN)
N16857806: R214.1 R215.2 U205.6(TRX_S)
N16857833: R214.2 U205.4(SSU_OUT)
N16857836: CC43.2 D43.2 U204.5(RFC)
N16857848: L21.2 U206.3(SSU_IN)
N16857851: R216.1 R217.2 U206.6(TRX_S)
N16857888: R216.2 U206.4(SSU_OUT)
N17007322: CDH3.2 LDH3.1 RDH2.1
N17033218: LED1.2(ANODE) R202.2
N17041538: C222.2 R207.2 U208.1(1A)
N17041550: C221.2 R206.2 U207.1(1A)

Not connected (* = marked no-connect by the designer): TPJ18 1(TP)*; TPJ19 1(TP)*; U200 C1(RESET#_/_SIO3); U205 10(NC1) 12(NC2) 29(NC3) 30(NC4) 31(NC5); U206 10(NC1) 12(NC2) 29(NC3) 30(NC4) 31(NC5)

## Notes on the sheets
sheet 2
- Board Function
- Page
- Title Page
- 1
- RF, Antenna & Power
- 2
- I/O Port Connections
- 3
- WSTK Connectors & Board ID
- 4
- Antenna Array
- 5
- LEGAL NOTICE:
  SILICON LABORATORIES INC. (“SILICON LABS”) AND/OR ITS LICENSORS DO NOT WARRANT THE ACCURACY
  OR COMPLETENESS OF THIS SCHEMATIC OR ANY INFORMATION CONTAINED WITHIN THIS SCHEMATIC.
  IT IS PROVIDED “AS-IS” FOR REFERENCE ONLY. SILICON LABS DOES NOT WARRANT THAT THIS DESIGN
  WILL MEET THE SPECIFICATIONS,  BE SUITABLE FOR YOUR APPLICATION OR FIT FOR ANY PARTICULAR
  PURPOSE, OR WILL OPERATE IN YOUR IMPLEMENTATION. SILICON LABS AND ITS LICENSORS DO NOT
  WARRANT THAT THE DESIGN IMPLIED IN THIS SCHEMATIC IS PRODUCTION-WORTHY. YOU SHOULD
  COMPLETELY VALIDATE AND TEST YOUR DESIGN IMPLEMENTATION TO CONFIRM SYSTEM FUNCTIONALITY
  FOR YOUR APPLICATION.
sheet 3
- EFR32 Pin Mapping
- EFR32 I/O Port Pins
- WSTK Peripheral
  Connection
- EFR32 Pin
- EFR32 Peripheral
- Low Frequency Crystal
- Serial Flash
- CHW Selection Signal Buffering
- CP/DP Signal Buffering
sheet 4
- CHW Output-Antenna Connections
sheet 5
- Antenna & Radio Interface
- PAVDD Configuration
- Power Config 1
  VMCU to PAVDD
- Power Config 2
  DCDC to PAVDD
- R203
- Mount
- Not mount
- R204
- Not mount
- Mount
- 2.4 GHz matching
        network
- High Frequency Crystal
- Overlay
  pads of
  R203/R204
- RF Shielding
- Power & Decoupling
sheet 6
- Simplicity Mini+ Connector
- Breakout Header
- WSTK Power Decoupling
- Test Points
